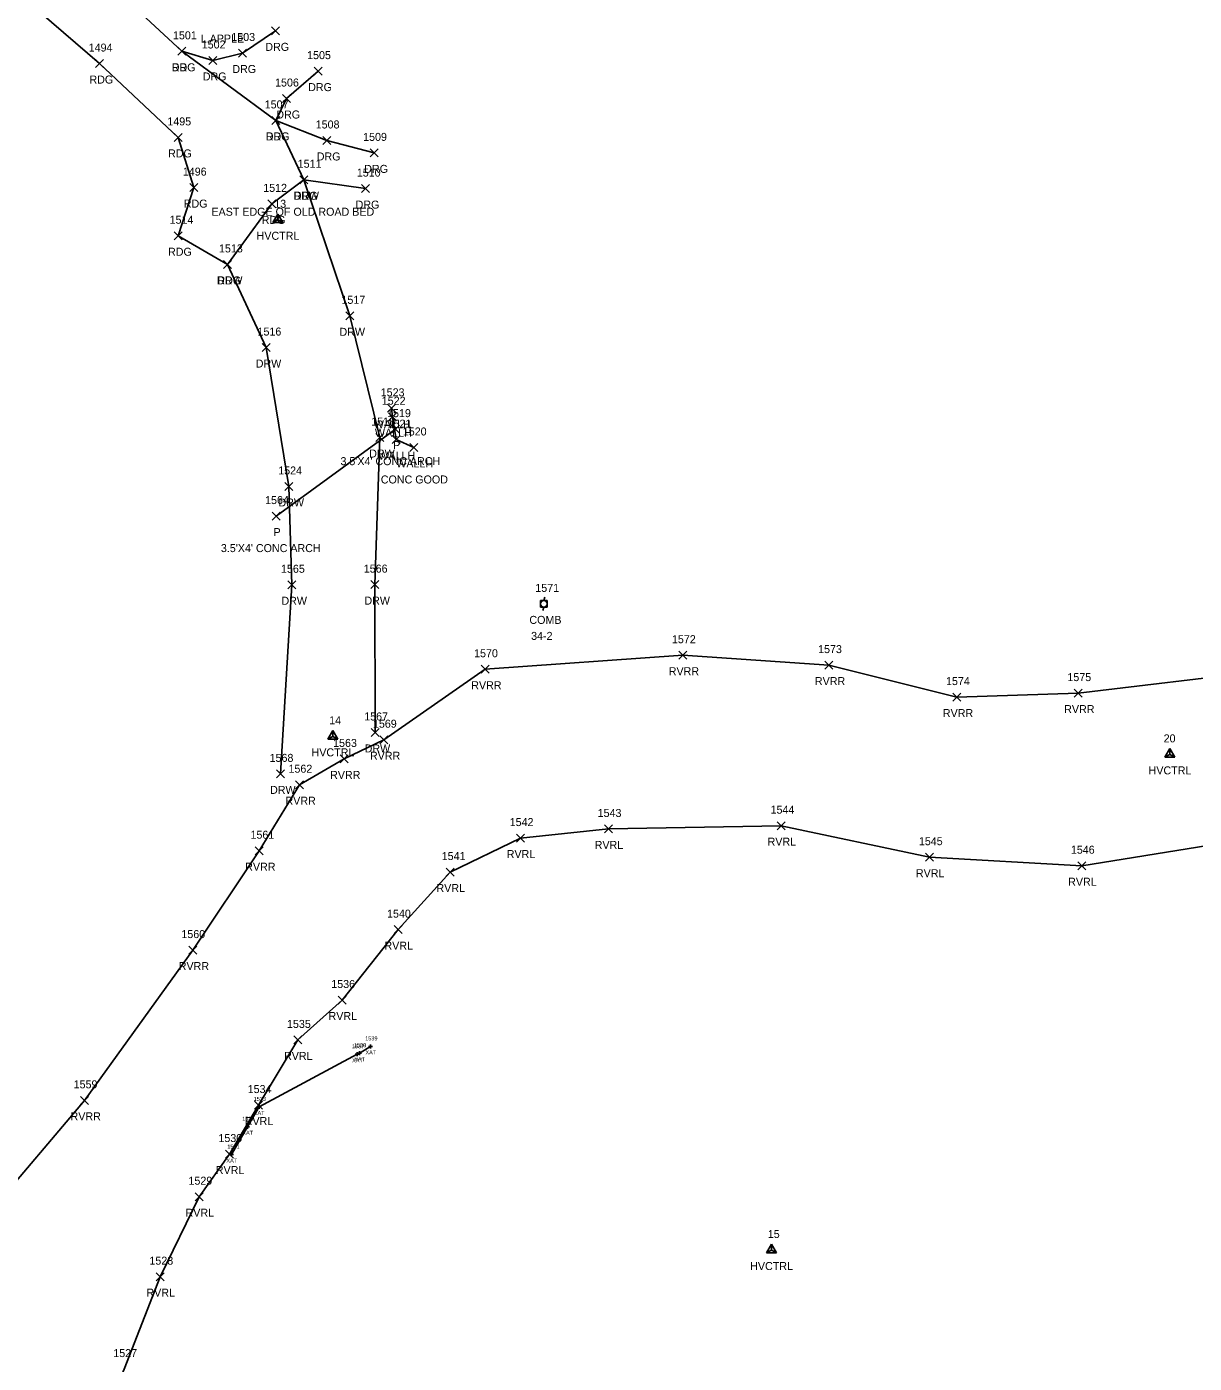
# Model space of a CAD drawing. Extents: x 1496556 to 1498241, y 599216 to 604470.
# Drawn here: x 1497255.4 to 1497547.4, y 603294.3 to 603628.4 of the extents above; entities that cross this region are included whole.
import ezdxf

# ---------------------------------------------------------------- set-up
doc = ezdxf.new("R2010")
doc.units = 0
for name, color, linetype in [('B_A', 7, 'Continuous'), ('B_I', 7, 'Continuous'), ('B_TIC', 7, 'Continuous'), ('BSUBM', 7, 'Continuous'), ('C_A', 7, 'Continuous'), ('C_I', 7, 'Continuous'), ('CPSM', 7, 'Continuous'), ('D_A', 7, 'Continuous'), ('D_C', 7, 'Continuous'), ('D_I', 7, 'Continuous'), ('D_TIC', 7, 'Continuous'), ('DCP', 7, 'Continuous'), ('DHW', 7, 'Continuous'), ('L_A', 7, 'Continuous'), ('L_C', 7, 'Continuous'), ('L_I', 7, 'Continuous'), ('L_TIC', 7, 'Continuous'), ('LAWE', 7, 'Continuous'), ('P_A', 7, 'Continuous'), ('P_I', 7, 'Continuous'), ('P_TIC', 7, 'Continuous'), ('PEU', 7, 'Continuous'), ('R_A', 7, 'Continuous'), ('R_C', 7, 'Continuous'), ('R_I', 7, 'Continuous'), ('R_TIC', 7, 'Continuous'), ('RDG', 7, 'Continuous'), ('RDW', 7, 'Continuous'), ('U_A', 7, 'Continuous'), ('U_C', 7, 'Continuous'), ('U_I', 7, 'Continuous'), ('UP', 7, 'Continuous')]:
    doc.layers.add(name, color=color, linetype=linetype)

msp = doc.modelspace()

# ---------------------------------------------------------------- linework, layer by layer
at = {"layer": 'B_TIC'}
for p, q in [((1497341.44, 603373.53), (1497341.52, 603373.53)), ((1497338.11, 603371.56), (1497338.18, 603371.56)), ((1497338.63, 603371.83), (1497338.71, 603371.83)), ((1497313.54, 603358.4), (1497313.61, 603358.4)), ((1497310.66, 603353.42), (1497310.74, 603353.42)), ((1497306.66, 603346.47), (1497306.74, 603346.47))]:
    msp.add_line(p, q, dxfattribs=at)
for points in [[(1497338.63, 603371.33), (1497338.63, 603372.33)], [(1497340.94, 603373.53), (1497341.94, 603373.53)], [(1497341.44, 603373.03), (1497341.44, 603374.03)], [(1497337.6, 603371.56), (1497338.6, 603371.56)], [(1497338.1, 603371.06), (1497338.1, 603372.06)], [(1497338.13, 603371.83), (1497339.13, 603371.83)], [(1497313.53, 603357.9), (1497313.53, 603358.9)], [(1497313.03, 603358.4), (1497314.03, 603358.4)], [(1497310.16, 603353.42), (1497311.16, 603353.42)], [(1497310.66, 603352.92), (1497310.66, 603353.92)], [(1497306.16, 603346.47), (1497307.16, 603346.47)], [(1497306.66, 603345.97), (1497306.66, 603346.97)]]:
    msp.add_lwpolyline(points, dxfattribs=at)
at = {"layer": 'BSUBM'}
msp.add_lwpolyline([(1497306.66, 603346.47), (1497310.66, 603353.42), (1497313.53, 603358.4), (1497338.1, 603371.56), (1497338.63, 603371.83), (1497341.44, 603373.53)], dxfattribs=at)
at = {"layer": 'CPSM'}
for p, q in [((1497316.99, 603579.44), (1497318.24, 603581.6)), ((1497316.99, 603579.44), (1497318.24, 603580.16)), ((1497316.99, 603579.44), (1497319.49, 603579.44)), ((1497319.49, 603579.44), (1497318.24, 603581.6)), ((1497318.24, 603580.16), (1497318.24, 603581.6)), ((1497318.24, 603580.16), (1497318.24, 603580.16)), ((1497318.24, 603580.16), (1497319.49, 603579.44)), ((1497330.72, 603450.31), (1497331.97, 603452.47)), ((1497333.22, 603450.31), (1497331.97, 603452.47)), ((1497331.98, 603451.03), (1497331.97, 603452.47)), ((1497330.72, 603450.31), (1497331.98, 603451.03)), ((1497330.72, 603450.31), (1497333.22, 603450.31)), ((1497331.98, 603451.03), (1497331.98, 603451.03)), ((1497331.98, 603451.03), (1497333.22, 603450.31)), ((1497540.06, 603445.8), (1497541.31, 603447.96)), ((1497540.06, 603445.8), (1497541.31, 603446.52)), ((1497540.06, 603445.8), (1497542.56, 603445.8)), ((1497542.56, 603445.8), (1497541.31, 603447.96)), ((1497541.31, 603446.52), (1497541.31, 603447.96)), ((1497541.31, 603446.52), (1497541.31, 603446.52)), ((1497541.31, 603446.52), (1497542.56, 603445.8)), ((1497440.42, 603321.89), (1497441.67, 603324.06)), ((1497440.42, 603321.89), (1497441.67, 603322.62)), ((1497442.92, 603321.89), (1497441.67, 603324.06)), ((1497441.67, 603322.62), (1497441.67, 603324.06)), ((1497441.67, 603322.62), (1497441.67, 603322.62)), ((1497441.67, 603322.62), (1497442.92, 603321.89)), ((1497440.42, 603321.89), (1497442.92, 603321.89))]:
    msp.add_line(p, q, dxfattribs=at)
at = {"layer": 'D_TIC'}
for points in [[(1497345.66, 603532.03), (1497347.66, 603534.03)], [(1497347.66, 603532.03), (1497345.66, 603534.03)], [(1497345.92, 603529.93), (1497347.92, 603531.93)], [(1497347.92, 603529.93), (1497345.92, 603531.93)], [(1497346.7, 603526.82), (1497348.7, 603528.82)], [(1497348.7, 603526.82), (1497346.7, 603528.82)], [(1497346.8, 603524.2), (1497348.8, 603526.2)], [(1497348.8, 603524.2), (1497346.8, 603526.2)], [(1497351.27, 603522.24), (1497353.27, 603524.24)], [(1497353.27, 603522.24), (1497351.27, 603524.24)], [(1497316.79, 603505.09), (1497318.79, 603507.09)], [(1497318.79, 603505.09), (1497316.79, 603507.09)]]:
    msp.add_lwpolyline(points, dxfattribs=at)
at = {"layer": 'DCP'}
msp.add_lwpolyline([(1497347.7, 603527.82), (1497317.79, 603506.09)], dxfattribs=at)
at = {"layer": 'DHW'}
msp.add_lwpolyline([(1497352.27, 603523.24), (1497347.8, 603525.2), (1497346.92, 603530.93), (1497346.66, 603533.03)], dxfattribs=at)
at = {"layer": 'L_TIC'}
for points in [[(1497418.49, 603470.31), (1497420.49, 603472.31)], [(1497420.49, 603470.31), (1497418.49, 603472.31)], [(1497455.04, 603467.84), (1497457.04, 603469.84)], [(1497457.04, 603467.84), (1497455.04, 603469.84)], [(1497369.1, 603466.8), (1497371.1, 603468.8)], [(1497371.1, 603466.8), (1497369.1, 603468.8)], [(1497517.38, 603460.84), (1497519.38, 603462.84)], [(1497519.38, 603460.84), (1497517.38, 603462.84)], [(1497487.04, 603459.85), (1497489.04, 603461.85)], [(1497489.04, 603459.85), (1497487.04, 603461.85)], [(1497343.77, 603449.19), (1497345.77, 603451.19)], [(1497345.77, 603449.19), (1497343.77, 603451.19)], [(1497333.8, 603444.38), (1497335.8, 603446.38)], [(1497335.8, 603444.38), (1497333.8, 603446.38)], [(1497322.64, 603437.94), (1497324.64, 603439.94)], [(1497324.64, 603437.94), (1497322.64, 603439.94)], [(1497443.15, 603427.7), (1497445.15, 603429.7)], [(1497445.15, 603427.7), (1497443.15, 603429.7)], [(1497377.91, 603424.6), (1497379.91, 603426.6)], [(1497379.91, 603424.6), (1497377.91, 603426.6)], [(1497399.91, 603426.88), (1497401.91, 603428.88)], [(1497401.91, 603426.88), (1497399.91, 603428.88)], [(1497312.57, 603421.44), (1497314.57, 603423.44)], [(1497314.57, 603421.44), (1497312.57, 603423.44)], [(1497480.24, 603419.82), (1497482.24, 603421.82)], [(1497482.24, 603419.82), (1497480.24, 603421.82)], [(1497518.31, 603417.69), (1497520.31, 603419.69)], [(1497520.31, 603417.69), (1497518.31, 603419.69)], [(1497360.35, 603416.11), (1497362.35, 603418.11)], [(1497362.35, 603416.11), (1497360.35, 603418.11)], [(1497347.33, 603401.71), (1497349.33, 603403.71)], [(1497349.33, 603401.71), (1497347.33, 603403.71)], [(1497295.95, 603396.6), (1497297.95, 603398.6)], [(1497297.95, 603396.6), (1497295.95, 603398.6)], [(1497333.35, 603384.12), (1497335.35, 603386.12)], [(1497335.35, 603384.12), (1497333.35, 603386.12)], [(1497322.23, 603374.14), (1497324.23, 603376.14)], [(1497324.23, 603374.14), (1497322.23, 603376.14)], [(1497268.89, 603359.04), (1497270.89, 603361.04)], [(1497270.89, 603359.04), (1497268.89, 603361.04)], [(1497312.39, 603357.86), (1497314.39, 603359.86)], [(1497314.39, 603357.86), (1497312.39, 603359.86)], [(1497305.16, 603345.61), (1497307.16, 603347.61)], [(1497307.16, 603345.61), (1497305.16, 603347.61)], [(1497297.59, 603334.95), (1497299.59, 603336.95)], [(1497299.59, 603334.95), (1497297.59, 603336.95)], [(1497287.82, 603314.96), (1497289.82, 603316.96)], [(1497289.82, 603314.96), (1497287.82, 603316.96)]]:
    msp.add_lwpolyline(points, dxfattribs=at)
at = {"layer": 'LAWE'}
for points in [[(1497189.81, 603091.49), (1497191.67, 603112.98), (1497209.98, 603150.46), (1497214.03, 603174.34), (1497209.01, 603206.37), (1497211.24, 603222.01), (1497227.45, 603268.03), (1497246.38, 603332.34), (1497269.89, 603360.04), (1497296.95, 603397.6), (1497313.57, 603422.44), (1497323.64, 603438.94), (1497334.8, 603445.38), (1497344.77, 603450.19), (1497370.1, 603467.8), (1497419.49, 603471.31), (1497456.04, 603468.84), (1497488.04, 603460.85), (1497518.38, 603461.84), (1497564.45, 603467.31)], [(1497257.29, 603233.96), (1497268.86, 603267.54), (1497279.78, 603292.86), (1497288.82, 603315.96), (1497298.59, 603335.95), (1497306.16, 603346.61), (1497313.39, 603358.86), (1497323.23, 603375.14), (1497334.35, 603385.12), (1497348.33, 603402.71), (1497361.35, 603417.11), (1497378.91, 603425.6), (1497400.91, 603427.88), (1497444.15, 603428.7), (1497481.24, 603420.82), (1497519.31, 603418.69), (1497550.81, 603423.71)]]:
    msp.add_lwpolyline(points, dxfattribs=at)
at = {"layer": 'P_TIC'}
for points in [[(1497293.22, 603621.27), (1497295.22, 603623.27)], [(1497295.22, 603621.27), (1497293.22, 603623.27)], [(1497272.63, 603618.21), (1497274.63, 603620.21)], [(1497274.63, 603618.21), (1497272.63, 603620.21)], [(1497316.74, 603604), (1497318.74, 603606)], [(1497318.74, 603604), (1497316.74, 603606)], [(1497292.31, 603599.75), (1497294.31, 603601.75)], [(1497294.31, 603599.75), (1497292.31, 603601.75)], [(1497323.77, 603589.17), (1497325.77, 603591.17)], [(1497325.77, 603589.17), (1497323.77, 603591.17)], [(1497296.23, 603587.2), (1497298.23, 603589.2)], [(1497298.23, 603587.2), (1497296.23, 603589.2)], [(1497315.71, 603583.14), (1497317.71, 603585.14)], [(1497317.71, 603583.14), (1497315.71, 603585.14)], [(1497292.3, 603575.17), (1497294.3, 603577.17)], [(1497294.3, 603575.17), (1497292.3, 603577.17)], [(1497292.3, 603575.17), (1497294.3, 603577.17)], [(1497294.3, 603575.17), (1497292.3, 603577.17)], [(1497304.64, 603568), (1497306.64, 603570)], [(1497306.64, 603568), (1497304.64, 603570)]]:
    msp.add_lwpolyline(points, dxfattribs=at)
at = {"layer": 'PEU'}
for points in [[(1496859.85, 603799.39), (1496865.05, 603796.5), (1496873.7, 603792.31), (1496883.54, 603793.48), (1496900.05, 603803.04), (1496919.62, 603816.41), (1496939.61, 603828.85), (1496964, 603841.16), (1496990.45, 603851.4), (1497013.22, 603849.84), (1497044.46, 603840.34), (1497066.94, 603824.52), (1497091.56, 603803.58), (1497125.12, 603773.26), (1497155.15, 603746.18), (1497220.12, 603687.84), (1497248.27, 603664.84), (1497294.22, 603622.27), (1497317.74, 603605), (1497324.77, 603590.17), (1497316.71, 603584.14), (1497305.64, 603569), (1497293.3, 603576.17)], [(1496891.52, 603741.51), (1496889.64, 603752.03), (1496894.84, 603769.23), (1496909.5, 603785.77), (1496931.96, 603802.73), (1496947.22, 603814.86), (1496973.09, 603827.29), (1496989.78, 603833.32), (1497015.57, 603832.12), (1497035.93, 603825.14), (1497055.45, 603810.85), (1497079.12, 603791.1), (1497113.06, 603759.28), (1497141.61, 603732.89), (1497273.63, 603619.21), (1497293.31, 603600.75), (1497297.23, 603588.2), (1497293.3, 603576.17)]]:
    msp.add_lwpolyline(points, dxfattribs=at)
at = {"layer": 'R_TIC'}
for points in [[(1497316.62, 603626.39), (1497318.62, 603628.39)], [(1497318.62, 603626.39), (1497316.62, 603628.39)], [(1497293.22, 603621.27), (1497295.22, 603623.27)], [(1497295.22, 603621.27), (1497293.22, 603623.27)], [(1497308.37, 603620.85), (1497310.37, 603622.85)], [(1497310.37, 603620.85), (1497308.37, 603622.85)], [(1497300.98, 603618.98), (1497302.98, 603620.98)], [(1497302.98, 603618.98), (1497300.98, 603620.98)], [(1497327.33, 603616.32), (1497329.33, 603618.32)], [(1497329.33, 603616.32), (1497327.33, 603618.32)], [(1497319.37, 603609.47), (1497321.37, 603611.47)], [(1497321.37, 603609.47), (1497319.37, 603611.47)], [(1497316.74, 603604), (1497318.74, 603606)], [(1497318.74, 603604), (1497316.74, 603606)], [(1497329.48, 603598.99), (1497331.48, 603600.99)], [(1497331.48, 603598.99), (1497329.48, 603600.99)], [(1497341.35, 603595.88), (1497343.35, 603597.88)], [(1497343.35, 603595.88), (1497341.35, 603597.88)], [(1497323.77, 603589.17), (1497325.77, 603591.17)], [(1497325.77, 603589.17), (1497323.77, 603591.17)], [(1497323.77, 603589.17), (1497325.77, 603591.17)], [(1497325.77, 603589.17), (1497323.77, 603591.17)], [(1497339.2, 603586.95), (1497341.2, 603588.95)], [(1497341.2, 603586.95), (1497339.2, 603588.95)], [(1497304.64, 603568), (1497306.64, 603570)], [(1497306.64, 603568), (1497304.64, 603570)], [(1497335.28, 603555.15), (1497337.28, 603557.15)], [(1497337.28, 603555.15), (1497335.28, 603557.15)], [(1497314.34, 603547.22), (1497316.34, 603549.22)], [(1497316.34, 603547.22), (1497314.34, 603549.22)], [(1497342.71, 603524.73), (1497344.71, 603526.73)], [(1497344.71, 603524.73), (1497342.71, 603526.73)], [(1497320.03, 603512.49), (1497322.03, 603514.49)], [(1497322.03, 603512.49), (1497320.03, 603514.49)], [(1497320.77, 603487.92), (1497322.77, 603489.92)], [(1497322.77, 603487.92), (1497320.77, 603489.92)], [(1497341.52, 603487.96), (1497343.52, 603489.96)], [(1497343.52, 603487.96), (1497341.52, 603489.96)], [(1497341.58, 603451), (1497343.58, 603453)], [(1497343.58, 603451), (1497341.58, 603453)], [(1497317.92, 603440.65), (1497319.92, 603442.65)], [(1497319.92, 603440.65), (1497317.92, 603442.65)]]:
    msp.add_lwpolyline(points, dxfattribs=at)
at = {"layer": 'RDG'}
for points in [[(1497294.22, 603622.27), (1497301.98, 603619.98), (1497309.37, 603621.85), (1497317.62, 603627.39)], [(1497328.33, 603617.32), (1497320.37, 603610.47), (1497317.74, 603605), (1497330.48, 603599.99), (1497342.35, 603596.88)], [(1497340.2, 603587.95), (1497324.77, 603590.17)]]:
    msp.add_lwpolyline(points, dxfattribs=at)
at = {"layer": 'RDW'}
for points in [[(1497324.77, 603590.17), (1497336.28, 603556.15), (1497343.71, 603525.73), (1497342.52, 603488.96), (1497342.58, 603452)], [(1497305.64, 603569), (1497315.34, 603548.22), (1497321.03, 603513.49), (1497321.77, 603488.92), (1497318.92, 603441.65)]]:
    msp.add_lwpolyline(points, dxfattribs=at)
at = {"layer": 'UP'}
for p, q in [((1497385.01, 603485.81), (1497384.76, 603484.97)), ((1497383.93, 603483.31), (1497383.93, 603484.97)), ((1497383.93, 603484.97), (1497385.59, 603484.97)), ((1497385.59, 603483.31), (1497383.93, 603483.31)), ((1497384.51, 603482.47), (1497384.76, 603483.31)), ((1497384.76, 603484.14), (1497384.76, 603484.14)), ((1497385.59, 603484.97), (1497385.59, 603483.31))]:
    msp.add_line(p, q, dxfattribs=at)
msp.add_circle((1497384.76, 603484.14), 0.833, dxfattribs=at)

# ---------------------------------------------------------------- texts
at = {"layer": 'B_A'}
for p in [(1497340.14, 603371.53), (1497336.81, 603369.56), (1497337.34, 603369.83), (1497312.24, 603356.4), (1497309.36, 603351.42), (1497305.37, 603344.47)]:
    msp.add_text('XAT', height=1, dxfattribs=at).set_placement(p)
at = {"layer": 'B_I'}
for s, p in [('1539', (1497340.09, 603375.03)), ('1537', (1497336.76, 603373.06)), ('1538', (1497337.28, 603373.33)), ('1533', (1497312.19, 603359.9)), ('1532', (1497309.31, 603354.92)), ('1531', (1497305.6, 603347.97))]:
    msp.add_text(s, height=1, dxfattribs=at).set_placement(p)
at = {"layer": 'C_A'}
for p in [(1497312.93, 603575.16), (1497326.67, 603446.03), (1497536, 603441.52), (1497436.36, 603317.62)]:
    msp.add_text('HVCTRL', height=2, dxfattribs=at).set_placement(p)
at = {"layer": 'C_I'}
for s, p in [('13', (1497317.34, 603583.16)), ('14', (1497331.08, 603454.03)), ('20', (1497539.76, 603449.52)), ('15', (1497440.77, 603325.62))]:
    msp.add_text(s, height=2, dxfattribs=at).set_placement(p)
at = {"layer": 'D_A'}
for s, p in [('WALLH', (1497342.25, 603528.03)), ('WALLH', (1497342.51, 603525.93)), ('P', (1497347.07, 603522.82)), ('WALLH', (1497343.39, 603520.2)), ('WALLH', (1497347.86, 603518.24)), ('P', (1497317.17, 603501.09))]:
    msp.add_text(s, height=2, dxfattribs=at).set_placement(p)
at = {"layer": 'D_C'}
for s, p in [("3.5'X4' CONC ARCH", (1497333.9, 603518.82)), ('CONC GOOD', (1497343.99, 603514.24)), ("3.5'X4' CONC ARCH", (1497304, 603497.09))]:
    msp.add_text(s, height=2, dxfattribs=at).set_placement(p)
at = {"layer": 'D_I'}
for s, p in [('1523', (1497343.97, 603536.03)), ('1522', (1497344.23, 603533.93)), ('1519', (1497345.56, 603530.82)), ('1521', (1497345.68, 603528.2)), ('1520', (1497349.49, 603526.24)), ('1564', (1497315.05, 603509.09))]:
    msp.add_text(s, height=2, dxfattribs=at).set_placement(p)
at = {"layer": 'L_A'}
for s, p in [('RVRR', (1497416, 603466.31)), ('RVRR', (1497452.55, 603463.84)), ('RVRR', (1497366.61, 603462.8)), ('RVRR', (1497484.55, 603455.85)), ('RVRR', (1497514.89, 603456.84)), ('RVRR', (1497341.28, 603445.19)), ('RVRR', (1497331.31, 603440.38)), ('RVRR', (1497320.15, 603433.94)), ('RVRL', (1497440.72, 603423.7)), ('RVRL', (1497375.48, 603420.6)), ('RVRL', (1497397.48, 603422.88)), ('RVRR', (1497310.08, 603417.44)), ('RVRL', (1497477.81, 603415.82)), ('RVRL', (1497515.88, 603413.69)), ('RVRL', (1497357.91, 603412.11)), ('RVRL', (1497344.9, 603397.71)), ('RVRR', (1497293.46, 603392.6)), ('RVRL', (1497330.92, 603380.12)), ('RVRL', (1497319.79, 603370.14)), ('RVRR', (1497266.4, 603355.04)), ('RVRL', (1497309.96, 603353.86)), ('RVRL', (1497302.73, 603341.61)), ('RVRL', (1497295.16, 603330.95)), ('RVRL', (1497285.38, 603310.96))]:
    msp.add_text(s, height=2, dxfattribs=at).set_placement(p)
at = {"layer": 'L_C'}
msp.add_text('L.APPLE', height=2, dxfattribs=at).set_placement((1497298.96, 603624.45))
at = {"layer": 'L_I'}
for s, p in [('1572', (1497416.79, 603474.31)), ('1570', (1497367.32, 603470.8)), ('1573', (1497453.35, 603471.84)), ('1574', (1497485.34, 603463.85)), ('1575', (1497515.69, 603464.84)), ('1569', (1497342.02, 603453.19)), ('1563', (1497332.06, 603448.38)), ('1562', (1497320.9, 603441.94)), ('1543', (1497398.22, 603430.88)), ('1544', (1497441.46, 603431.7)), ('1542', (1497376.22, 603428.6)), ('1561', (1497311.4, 603425.44)), ('1545', (1497478.55, 603423.82)), ('1546', (1497516.56, 603421.69)), ('1541', (1497359.22, 603420.11)), ('1540', (1497345.55, 603405.71)), ('1560', (1497294.12, 603400.6)), ('1536', (1497331.6, 603388.12)), ('1535', (1497320.53, 603378.14)), ('1559', (1497267.18, 603363.04)), ('1534', (1497310.7, 603361.86)), ('1530', (1497303.38, 603349.61)), ('1529', (1497295.89, 603338.95)), ('1528', (1497286.12, 603318.96)), ('1527', (1497277.09, 603295.86))]:
    msp.add_text(s, height=2, dxfattribs=at).set_placement(p)
at = {"layer": 'P_A'}
for p in [(1497271.12, 603614.21), (1497291.71, 603617.27), (1497315.22, 603600), (1497290.79, 603595.75), (1497322.26, 603585.17), (1497294.71, 603583.2), (1497314.2, 603579.14), (1497290.78, 603571.17), (1497290.78, 603571.17), (1497303.13, 603564)]:
    msp.add_text('RDG', height=2, dxfattribs=at).set_placement(p)
at = {"layer": 'P_I'}
for s, p in [('1501', (1497292.02, 603625.27)), ('1494', (1497270.94, 603622.21)), ('1507', (1497314.96, 603608)), ('1495', (1497290.61, 603603.75)), ('1496', (1497294.48, 603591.2)), ('1511', (1497323.21, 603593.17)), ('1512', (1497314.58, 603587.14)), ('1514', (1497291.17, 603579.17)), ('1514', (1497291.17, 603579.17)), ('1513', (1497303.52, 603572))]:
    msp.add_text(s, height=2, dxfattribs=at).set_placement(p)
at = {"layer": 'R_A'}
for s, p in [('DRG', (1497315.11, 603622.39)), ('DRG', (1497291.71, 603617.27)), ('DRG', (1497299.47, 603614.98)), ('DRG', (1497306.86, 603616.85)), ('DRG', (1497325.82, 603612.32)), ('DRG', (1497317.86, 603605.47)), ('DRG', (1497315.22, 603600)), ('DRG', (1497327.97, 603594.99)), ('DRG', (1497339.84, 603591.88)), ('DRW', (1497322.14, 603585.17)), ('DRG', (1497322.26, 603585.17)), ('DRG', (1497337.69, 603582.95)), ('DRW', (1497303.01, 603564)), ('DRW', (1497333.65, 603551.15)), ('DRW', (1497312.71, 603543.22)), ('DRW', (1497341.08, 603520.73)), ('DRW', (1497318.4, 603508.49)), ('DRW', (1497319.14, 603483.92)), ('DRW', (1497339.89, 603483.96)), ('DRW', (1497339.95, 603447)), ('DRW', (1497316.29, 603436.65))]:
    msp.add_text(s, height=2, dxfattribs=at).set_placement(p)
at = {"layer": 'R_C'}
msp.add_text('EAST EDGE OF OLD ROAD BED', height=2, dxfattribs=at).set_placement((1497301.63, 603581.17))
at = {"layer": 'R_I'}
for s, p in [('1501', (1497292.02, 603625.27)), ('1503', (1497306.6, 603624.85)), ('1502', (1497299.21, 603622.98)), ('1505', (1497325.56, 603620.32)), ('1506', (1497317.55, 603613.47)), ('1507', (1497314.96, 603608)), ('1508', (1497327.71, 603602.99)), ('1509', (1497339.57, 603599.88)), ('1511', (1497323.21, 603593.17)), ('1511', (1497323.21, 603593.17)), ('1510', (1497337.99, 603590.95)), ('1513', (1497303.52, 603572)), ('1517', (1497334.15, 603559.15)), ('1516', (1497313.16, 603551.22)), ('1518', (1497341.58, 603528.73)), ('1524', (1497318.33, 603516.49)), ('1565', (1497319.03, 603491.92)), ('1566', (1497339.73, 603491.96)), ('1567', (1497339.84, 603455)), ('1568', (1497316.18, 603444.65))]:
    msp.add_text(s, height=2, dxfattribs=at).set_placement(p)
at = {"layer": 'U_A'}
msp.add_text('COMB', height=2, dxfattribs=at).set_placement((1497381.15, 603479.14))
at = {"layer": 'U_C'}
msp.add_text('34-2', height=2, dxfattribs=at).set_placement((1497381.58, 603475.14))
at = {"layer": 'U_I'}
msp.add_text('1571', height=2, dxfattribs=at).set_placement((1497382.63, 603487.14))

doc.saveas('drawing.dxf')
